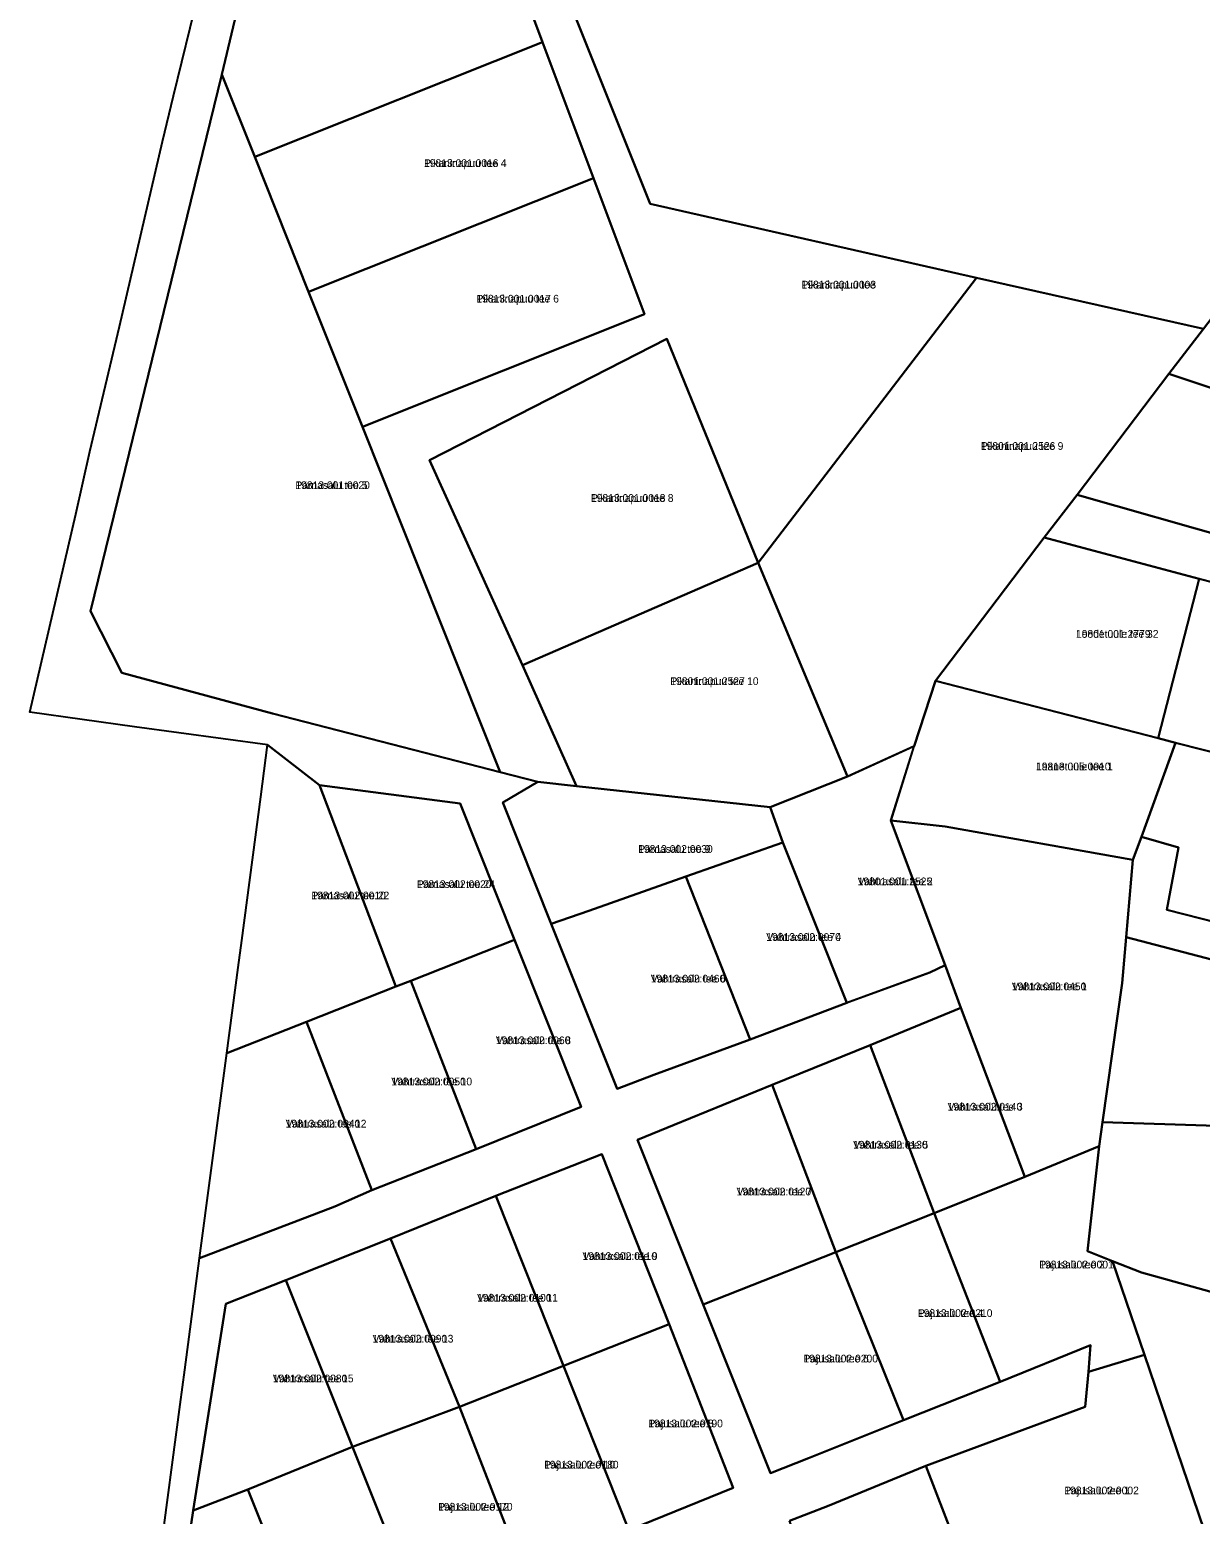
# Model space of a CAD drawing. Extents: x 516875 to 535633, y 6574491 to 6593094.
# Drawn here: x 517422.8 to 517650.6, y 6583914.7 to 6584203.6 of the extents above; entities that cross this region are included whole.
import ezdxf

# ---------------------------------------------------------------- set-up
doc = ezdxf.new("R2010")
doc.units = 0
for name, color, linetype in [('L_AADRESS', 7, 'Continuous'), ('PIIR', 7, 'Continuous'), ('TUNNUS', 7, 'Continuous')]:
    doc.layers.add(name, color=color, linetype=linetype)

msp = doc.modelspace()

# ---------------------------------------------------------------- linework, layer by layer
at = {"layer": 'PIIR'}
for points in [[(517473.32, 6584250.05), (517481.27, 6584249.21), (517513.07, 6584245.83), (517543.49, 6584169.71), (517607.05, 6584155.33), (517564.54, 6584099.9), (517546.79, 6584143.48), (517500.6, 6584119.85), (517518.66, 6584079.99), (517529.17, 6584056.45), (517521.64, 6584057.28), (517514.32, 6584059.16), (517487.52, 6584126.33), (517542.4, 6584148.23), (517532.48, 6584174.71), (517522.56, 6584201.2), (517511.01, 6584232.05), (517503.73, 6584237.78), (517500.78, 6584238.65), (517470.83, 6584239.94)], [(517470.83, 6584239.94), (517500.78, 6584238.65), (517503.73, 6584237.78), (517511.01, 6584232.05), (517522.56, 6584201.2), (517466.56, 6584178.85), (517460.16, 6584194.91)], [(517466.56, 6584178.85), (517522.56, 6584201.2), (517532.48, 6584174.71), (517477.04, 6584152.59)], [(517460.16, 6584194.91), (517466.56, 6584178.85), (517477.04, 6584152.59), (517487.52, 6584126.33), (517514.32, 6584059.16), (517470.02, 6584070.57), (517440.71, 6584078.48), (517434.61, 6584090.46)], [(517532.48, 6584174.71), (517542.4, 6584148.23), (517487.52, 6584126.33), (517477.04, 6584152.59)], [(517594.89, 6584064.17), (517581.91, 6584058.31), (517564.54, 6584099.9), (517607.05, 6584155.33), (517651.21, 6584145.42), (517644.46, 6584136.64), (517626.64, 6584113.1), (517620.18, 6584104.83), (517599.06, 6584076.92)], [(517660.88, 6584158.06), (517689.39, 6584147.67), (517673.82, 6584126.88), (517644.46, 6584136.64), (517651.21, 6584145.42)], [(517546.79, 6584143.48), (517564.54, 6584099.9), (517518.66, 6584079.99), (517500.6, 6584119.85)], [(517644.46, 6584136.64), (517673.82, 6584126.88), (517657.18, 6584104.43), (517626.64, 6584113.1)], [(517599.06, 6584076.92), (517620.18, 6584104.83), (517650.35, 6584096.77), (517642.38, 6584065.75)], [(517564.54, 6584099.9), (517581.91, 6584058.31), (517566.85, 6584052.3), (517529.17, 6584056.45), (517518.66, 6584079.99)], [(517650.35, 6584096.77), (517675.23, 6584090.42), (517666.8, 6584059.53), (517645.75, 6584064.86), (517642.38, 6584065.75)], [(517642.38, 6584065.75), (517645.75, 6584064.86), (517639.15, 6584046.56), (517637.48, 6584042.08), (517600.94, 6584048.57), (517590.34, 6584049.74), (517594.89, 6584064.17), (517599.06, 6584076.92)], [(517467.75, 6584054.35), (517469.06, 6584064.43), (517479.15, 6584056.6), (517494.03, 6584017.43), (517476.62, 6584010.59), (517461.1, 6584004.49), (517463.31, 6584021.14), (517464.01, 6584026.37)], [(517566.85, 6584052.3), (517581.91, 6584058.31), (517594.84, 6584064.22), (517590.34, 6584049.74), (517600.96, 6584021.57), (517597.98, 6584020.16), (517581.78, 6584014.28), (517569.33, 6584045.43)], [(517646.35, 6584044.51), (517639.15, 6584046.56), (517645.75, 6584064.86), (517666.8, 6584059.53), (517673.97, 6584057.62), (517666.74, 6584026.6), (517644.05, 6584032.34)], [(517514.83, 6584053.24), (517521.64, 6584057.28), (517529.17, 6584056.45), (517566.85, 6584052.3), (517569.33, 6584045.43), (517550.46, 6584038.83), (517531.6, 6584032.18), (517524.27, 6584029.6)], [(517496.92, 6584018.57), (517494.03, 6584017.43), (517479.15, 6584056.6), (517506.55, 6584053.06), (517517.12, 6584026.52)], [(517604, 6584013.27), (517600.96, 6584021.57), (517590.34, 6584049.74), (517600.94, 6584048.57), (517637.48, 6584042.08), (517636.16, 6584027.04), (517635.38, 6584018.08), (517631.57, 6583991.05), (517630.91, 6583986.34), (517616.47, 6583980.4)], [(517550.46, 6584038.83), (517569.33, 6584045.43), (517581.78, 6584014.28), (517563, 6584007.14)], [(517524.27, 6584029.6), (517531.6, 6584032.18), (517550.46, 6584038.83), (517563, 6584007.14), (517544.23, 6584000.23), (517537.07, 6583997.55)], [(517496.92, 6584018.57), (517517.12, 6584026.52), (517530.06, 6583994.05), (517509.67, 6583985.81)], [(517675.35, 6584016.77), (517676.59, 6584009.38), (517675.92, 6583989.6), (517631.57, 6583991.05), (517635.38, 6584018.08), (517636.16, 6584027.04)], [(517476.62, 6584010.59), (517494.03, 6584017.43), (517496.92, 6584018.57), (517509.67, 6583985.81), (517489.36, 6583977.84)], [(517586.37, 6584006.04), (517604, 6584013.27), (517616.47, 6583980.4), (517598.77, 6583973.34)], [(517461.1, 6584004.49), (517476.62, 6584010.59), (517489.36, 6583977.84), (517482.15, 6583974.65), (517455.8, 6583964.57), (517458.07, 6583981.66)], [(517598.77, 6583973.34), (517579.63, 6583965.76), (517567.29, 6583998.3), (517586.37, 6584006.04)], [(517541.05, 6583987.59), (517548.17, 6583990.5), (517567.29, 6583998.3), (517579.63, 6583965.76), (517560.92, 6583958.35), (517553.85, 6583955.55)], [(517675.92, 6583989.6), (517675.15, 6583964.07), (517691.62, 6583947.17), (517639.15, 6583961.76), (517633.5, 6583964.01), (517628.61, 6583965.96), (517630.91, 6583986.34), (517631.57, 6583991.05)], [(517559.67, 6583919.88), (517547.24, 6583951.73), (517534.09, 6583984.84), (517513.47, 6583976.73), (517492.99, 6583968.39), (517472.62, 6583960.31), (517460.94, 6583955.68), (517454.55, 6583915.46), (517448.67, 6583875.33), (517478.2, 6583887.16), (517498.61, 6583895.33), (517518.88, 6583903.6), (517539.35, 6583911.66)], [(517526.67, 6583943.63), (517513.47, 6583976.73), (517534.09, 6583984.84), (517547.24, 6583951.73)], [(517616.47, 6583980.4), (517630.91, 6583986.34), (517628.61, 6583965.96), (517633.5, 6583964.01), (517639.72, 6583945.75), (517628.84, 6583942.47), (517629.23, 6583947.66), (517611.66, 6583940.54), (517598.77, 6583973.34)], [(517526.67, 6583943.63), (517506.38, 6583935.64), (517492.99, 6583968.39), (517513.47, 6583976.73)], [(517579.63, 6583965.76), (517598.77, 6583973.34), (517611.66, 6583940.54), (517592.85, 6583933.06)], [(517472.62, 6583960.31), (517492.99, 6583968.39), (517506.38, 6583935.64), (517485.6, 6583927.85)], [(517553.85, 6583955.55), (517560.92, 6583958.35), (517579.63, 6583965.76), (517592.85, 6583933.06), (517574.31, 6583925.69), (517566.94, 6583922.76)], [(517639.15, 6583961.76), (517691.62, 6583947.17), (517703.49, 6583914.48), (517699.43, 6583912.76), (517656.57, 6583896.21), (517639.72, 6583945.75), (517633.5, 6583964.01)], [(517460.94, 6583955.68), (517472.62, 6583960.31), (517485.6, 6583927.85), (517465.19, 6583919.56), (517454.55, 6583915.46)], [(517526.67, 6583943.63), (517547.24, 6583951.73), (517559.67, 6583919.88), (517539.35, 6583911.66)], [(517628.18, 6583935.68), (517628.84, 6583942.47), (517639.72, 6583945.75), (517656.57, 6583896.21), (517622.15, 6583896.61), (517620.01, 6583895.71), (517609.77, 6583891.52), (517597.18, 6583924.18)], [(517506.38, 6583935.64), (517526.67, 6583943.63), (517539.35, 6583911.66), (517518.88, 6583903.6)], [(517485.6, 6583927.85), (517506.38, 6583935.64), (517518.88, 6583903.6), (517498.61, 6583895.33)], [(517465.19, 6583919.56), (517485.6, 6583927.85), (517498.61, 6583895.33), (517478.2, 6583887.16)], [(517570.65, 6583913.48), (517578.04, 6583916.34), (517597.18, 6583924.18), (517609.77, 6583891.52), (517591.14, 6583883.89), (517583.68, 6583880.84)], [(517478.2, 6583887.16), (517448.67, 6583875.33), (517454.55, 6583915.46), (517465.19, 6583919.56)]]:
    msp.add_lwpolyline(points, close=True, dxfattribs=at)
for points in [[(518018.27, 6584114.96), (517991.96, 6584121.14), (517962.35, 6584127.9), (517934.79, 6584134.3), (517910.52, 6584139.88), (517884.62, 6584147.65), (517860.28, 6584154.5), (517820.61, 6584165.03), (517778.25, 6584176.21), (517745.66, 6584186.23), (517736.59, 6584188.6), (517712.21, 6584194.93), (517692.86, 6584199.83), (517665.96, 6584164.7), (517660.88, 6584158.06), (517651.21, 6584145.42), (517607.05, 6584155.33), (517543.49, 6584169.71), (517513.07, 6584245.83)], [(517470.83, 6584239.94), (517460.16, 6584194.91), (517434.61, 6584090.46), (517440.71, 6584078.48), (517470.02, 6584070.57), (517514.32, 6584059.16), (517521.64, 6584057.28), (517514.83, 6584053.24), (517524.27, 6584029.6), (517537.07, 6583997.55), (517544.23, 6584000.23), (517563, 6584007.14), (517581.78, 6584014.28), (517582.08, 6584014.39), (517597.98, 6584020.16), (517600.96, 6584021.57), (517604, 6584013.27), (517586.37, 6584006.04), (517567.29, 6583998.3), (517548.17, 6583990.5), (517541.05, 6583987.59), (517553.85, 6583955.55), (517566.94, 6583922.76), (517574.31, 6583925.69), (517592.85, 6583933.06), (517611.66, 6583940.54), (517629.23, 6583947.66), (517628.84, 6583942.47), (517628.18, 6583935.68), (517597.18, 6583924.18), (517578.04, 6583916.34), (517570.65, 6583913.48)], [(517448.07, 6583906.29), (517452.02, 6583936.11), (517452.92, 6583942.86), (517455.8, 6583964.57), (517482.15, 6583974.65), (517489.36, 6583977.84), (517509.67, 6583985.81), (517530.06, 6583994.05), (517517.12, 6584026.52), (517506.55, 6584053.06), (517479.15, 6584056.6), (517469.06, 6584064.43), (517443.15, 6584067.99), (517422.75, 6584070.79), (517431.76, 6584109.37), (517434.46, 6584121.52), (517440.22, 6584145.87), (517448.63, 6584181.84), (517450.71, 6584190.75), (517460.45, 6584230.48)], [(517675.23, 6584090.42), (517650.35, 6584096.77), (517620.18, 6584104.83), (517626.64, 6584113.1), (517657.18, 6584104.43)], [(517675.35, 6584016.77), (517636.16, 6584027.04), (517637.48, 6584042.08), (517639.15, 6584046.56), (517646.35, 6584044.51), (517644.05, 6584032.34), (517666.74, 6584026.6)]]:
    msp.add_lwpolyline(points, dxfattribs=at)

# ---------------------------------------------------------------- texts
at = {"layer": 'L_AADRESS'}
for s, p in [('Pikaninapuu tee 4', (517499.5, 6584176.9)), ('Pikaninapuu tee', (517572.99, 6584153.25)), ('Pikaninapuu tee 6', (517509.7, 6584150.52)), ('Pikaninapuu tee 9', (517607.88, 6584121.86)), ('Pärnasalu tee 5', (517474.46, 6584114.23)), ('Pikaninapuu tee 8', (517532, 6584111.74)), ('Loodetuule tee 32', (517626.4, 6584085.29)), ('Pikaninapuu tee 10', (517547.44, 6584076.1)), ('Läänetuule tee 1', (517618.62, 6584059.5)), ('Pärnasalu tee 9', (517541.19, 6584043.44)), ('Pärnasalu tee 24', (517498.13, 6584036.6)), ('Vahtrasalu tee 2', (517583.91, 6584037.14)), ('Pärnasalu tee 22', (517477.57, 6584034.4)), ('Vahtrasalu tee 4', (517566.12, 6584026.32)), ('Vahtrasalu tee 6', (517543.64, 6584018.22)), ('Vahtrasalu tee 1', (517613.91, 6584016.71)), ('Vahtrasalu tee 8', (517513.49, 6584006.22)), ('Vahtrasalu tee 10', (517493.14, 6583998.2)), ('Vahtrasalu tee 3', (517601.42, 6583993.3)), ('Vahtrasalu tee 12', (517472.58, 6583990)), ('Vahtrasalu tee 5', (517583.03, 6583985.9)), ('Vahtrasalu tee 7', (517560.34, 6583976.79)), ('Vahtrasalu tee 9', (517530.36, 6583964.23)), ('Pajusalu tee 2', (517619.25, 6583962.58)), ('Vahtrasalu tee 11', (517509.83, 6583956.12)), ('Pajusalu tee 4', (517595.64, 6583953.14)), ('Vahtrasalu tee 13', (517489.5, 6583948.16)), ('Pajusalu tee 6', (517573.35, 6583944.29)), ('Vahtrasalu tee 15', (517470.07, 6583940.42)), ('Pajusalu tee 8', (517543.17, 6583931.67)), ('Pajusalu tee 10', (517522.87, 6583923.65)), ('Pajusalu tee 1', (517624.13, 6583918.63)), ('Pajusalu tee 12', (517502.24, 6583915.45))]:
    msp.add_text(s, height=1.5, dxfattribs=at).set_placement(p)
at = {"layer": 'TUNNUS'}
for s, p in [('19813:001:0016', (517499.5, 6584176.9)), ('19813:001:0003', (517572.99, 6584153.25)), ('19813:001:0017', (517509.7, 6584150.52)), ('19801:001:2526', (517607.88, 6584121.86)), ('19813:001:0020', (517474.46, 6584114.23)), ('19813:001:0018', (517532, 6584111.74)), ('19801:001:2779', (517626.4, 6584085.29)), ('19801:001:2527', (517547.44, 6584076.1)), ('19813:005:0010', (517618.62, 6584059.5)), ('19813:002:0030', (517541.19, 6584043.44)), ('19813:002:0020', (517498.13, 6584036.6)), ('19801:001:2525', (517583.91, 6584037.14)), ('19813:002:0010', (517477.57, 6584034.4)), ('19813:002:0070', (517566.12, 6584026.32)), ('19813:002:0460', (517543.64, 6584018.22)), ('19813:002:0450', (517613.91, 6584016.71)), ('19813:002:0060', (517513.49, 6584006.22)), ('19813:002:0050', (517493.14, 6583998.2)), ('19813:002:0140', (517601.42, 6583993.3)), ('19813:002:0040', (517472.58, 6583990)), ('19813:002:0130', (517583.03, 6583985.9)), ('19813:002:0120', (517560.34, 6583976.79)), ('19813:002:0110', (517530.36, 6583964.23)), ('19813:002:0001', (517619.25, 6583962.58)), ('19813:002:0100', (517509.83, 6583956.12)), ('19813:002:0210', (517595.64, 6583953.14)), ('19813:002:0090', (517489.5, 6583948.16)), ('19813:002:0200', (517573.35, 6583944.29)), ('19813:002:0080', (517470.07, 6583940.42)), ('19813:002:0190', (517543.17, 6583931.67)), ('19813:002:0180', (517522.87, 6583923.65)), ('19813:002:0002', (517624.13, 6583918.63)), ('19813:002:0170', (517502.24, 6583915.45))]:
    msp.add_text(s, height=1.5, dxfattribs=at).set_placement(p)

doc.saveas('drawing.dxf')
